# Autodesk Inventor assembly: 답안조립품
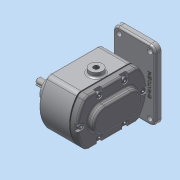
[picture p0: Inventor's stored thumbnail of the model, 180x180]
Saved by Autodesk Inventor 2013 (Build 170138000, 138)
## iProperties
Created: 2019-03
Part Number: 답안조립품
Document SubType Name: Assembly
Designer: Administrator
Author: Administrator
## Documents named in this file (12)
- C:\Users\Administrator\Desktop\490307V1001\답안조립품.iam
- C:\Users\Administrator\Desktop\490307V1001\개스킷 - 복사본.ipt
- C:\Users\Administrator\Desktop\490307V1001\개스킷.ipt
- C:\Users\Administrator\Desktop\490307V1001\메인축.ipt
- C:\Users\Administrator\Desktop\490307V1001\베어링부시.ipt
- C:\Users\Administrator\Desktop\490307V1001\본체.ipt
- C:\Users\Administrator\Desktop\490307V1001\볼트 M5.ipt
- C:\Users\Administrator\Desktop\490307V1001\서브축.ipt
- C:\Users\Administrator\Desktop\490307V1001\스퍼기어.ipt
- C:\Users\Administrator\Desktop\490307V1001\오일 실 16 28 7.ipt
- C:\Users\Administrator\Desktop\490307V1001\커버.ipt
- C:\Users\Administrator\Desktop\490307V1001\키 6 x 6 x 18.ipt
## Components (2 placed, 2 different names)
1. 개스킷 - 복사본:1
2. 개스킷:1
